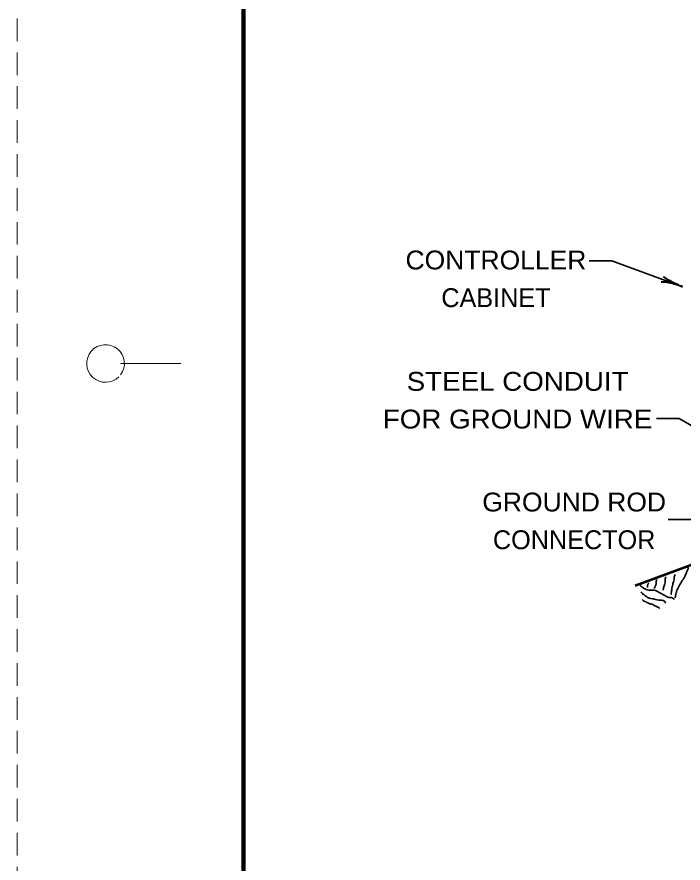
# Model space of a CAD drawing. Extents: x 12366 to 13046, y 9129 to 9570.
# Drawn here: x 12365.9 to 12454.3, y 9349.5 to 9461.7 of the extents above; entities that cross this region are included whole.
import ezdxf
from ezdxf.enums import TextEntityAlignment as Align

# ---------------------------------------------------------------- set-up
doc = ezdxf.new("R2010")
doc.units = 0
doc.linetypes.add('MEDIUM_DASHED', pattern=[4.5, 3, -1.5])
doc.layers.add('1', color=7, linetype='Continuous', lineweight=53)
doc.layers.add('61', color=7, linetype='Continuous', lineweight=35)

msp = doc.modelspace()

# ---------------------------------------------------------------- linework, layer by layer
at = {"layer": '1', "linetype": 'MEDIUM_DASHED', "lineweight": 13}
msp.add_line((12365.992, 9569.533), (12365.932, 9129.493), dxfattribs=at)
at = {"layer": '1', "lineweight": 35}
msp.add_line((12458.935, 9395.086), (12452.316, 9395.102), dxfattribs=at)
at = {"layer": '1'}
msp.add_line((12469.382, 9394.167), (12447.947, 9386.3), dxfattribs=at)
at = {"layer": '1', "lineweight": 35}
for points in [[(12454.214, 9425.961), (12444.817, 9429.382), (12441.817, 9429.382)], [(12458.95, 9405.472), (12453.754, 9408.472), (12450.754, 9408.472)]]:
    msp.add_lwpolyline(points, dxfattribs=at)
at = {"layer": '1', "lineweight": 40}
for centre, major_axis, ratio, start_param, end_param in [((12453.233, 9426.544), (-1.59, 0.766), 0.07063, 6.2823074, 8.5597026), ((12453.094, 9426.075), (1.731, -0.464), 0.122415, 0.8963533, 3.1415927)]:
    msp.add_ellipse(centre, major_axis=major_axis, ratio=ratio, start_param=start_param, end_param=end_param, dxfattribs=at)
at = {"layer": '1', "lineweight": 35}
for points in [[(12454.883, 9388.843), (12454.931, 9388.725), (12454.943, 9388.522), (12454.872, 9388.356), (12454.8, 9388.19), (12454.658, 9387.857), (12454.551, 9387.608), (12454.183, 9386.978), (12453.981, 9386.621), (12453.577, 9385.908), (12453.435, 9385.576), (12453.387, 9385.35), (12453.304, 9385.041), (12453.245, 9384.673)], [(12453.247, 9387.766), (12453.099, 9387.362), (12453.081, 9386.976), (12452.95, 9386.614), (12452.879, 9386.275), (12452.784, 9385.996), (12452.778, 9385.753), (12452.743, 9385.497), (12452.713, 9385.141)], [(12449.713, 9386.696), (12449.671, 9386.542), (12449.642, 9386.53), (12449.606, 9386.447), (12449.564, 9386.12), (12449.559, 9386.049)], [(12450.824, 9387.107), (12450.705, 9386.887), (12450.705, 9386.715), (12450.717, 9386.512), (12450.646, 9386.346), (12450.61, 9386.263), (12450.426, 9385.948)], [(12452.017, 9387.481), (12451.911, 9387.232), (12451.911, 9386.887), (12451.881, 9386.531), (12451.697, 9386.043), (12451.65, 9385.818), (12451.626, 9385.705)], [(12448.617, 9386.335), (12449.544, 9385.741), (12450.459, 9385.694), (12451.124, 9385.409), (12451.481, 9385.207), (12451.92, 9384.97), (12452.277, 9384.768), (12452.704, 9384.732), (12453.144, 9384.495)], [(12448.709, 9385.502), (12448.971, 9385.193), (12449.363, 9384.902), (12449.814, 9384.635), (12450.183, 9384.576), (12450.83, 9384.422), (12451.846, 9384.208), (12451.971, 9383.982)], [(12448.852, 9384.457), (12449.054, 9384.296), (12449.387, 9384.154), (12449.826, 9383.916), (12450.165, 9383.845), (12450.521, 9383.643), (12450.854, 9383.501), (12451.211, 9383.299)]]:
    msp.add_spline(points, degree=3, dxfattribs=at)
at = {"layer": '61', "lineweight": 13}
msp.add_line((12379.692, 9415.773), (12387.692, 9415.773), dxfattribs=at)
at = {"layer": '61', "lineweight": 158}
msp.add_lwpolyline([(13035.032, 9559.533), (12395.992, 9559.533), (12395.992, 9139.513)], dxfattribs=at)
at = {"layer": '61', "lineweight": 13}
msp.add_arc((12377.689, 9415.774), 2.5, 323.13009, 315.37577, dxfattribs=at)

# ---------------------------------------------------------------- texts
at = {"layer": '1'}
for s, width, p in [('CONTROLLER', 1.05, (12429.467, 9428.249)), ('STEEL CONDUIT', 1.1, (12432.341, 9412.151)), ('FOR GROUND WIRE', 1.1, (12432.341, 9407.151)), ('GROUND ROD', 1.05, (12439.842, 9396.148))]:
    msp.add_text(s, height=2.5, dxfattribs=dict(at, width=width)).set_placement(p, align=Align.CENTER)
for s, p in [('CABINET', (12429.467, 9423.249)), ('CONNECTOR', (12439.842, 9391.148))]:
    msp.add_text(s, height=2.5, dxfattribs=at).set_placement(p, align=Align.CENTER)

doc.saveas('drawing.dxf')
